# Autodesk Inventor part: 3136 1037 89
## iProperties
Shininess: 25.0
Length Units: 11269
Angle Units: 11279
Time Units: 11290
Mass Units: 11283
Length Display Precision: 3
Angle Display Precision: 2
Compacted: True
Created: 2001-04
Part Number: 3136 1037 89
Material: Steel, Mild
Document SubType Name: Sheet Metal
Designer: Joe M
Description: Packing strap
Engineer: Joe M
Density: 0.0
Volumn: 0.0
Area: 0.0
PropertySet Name: Model Information
Control State: 0
Master: False
Checked Out: False
Last Check In Date: 2001-08-01
Last Check In By: brjdn
Title: Packrem
Author: Joe M
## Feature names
1. Extrusion2
2. Hole1
3. Extrusion3
4. Extrusion4
5. Extrusion5
6. Plate1
7. Plate2
8. Bend1
9. Plate3
10. Bend2
11. Plate4
12. Bend3
13. Plate5
14. Bend4
